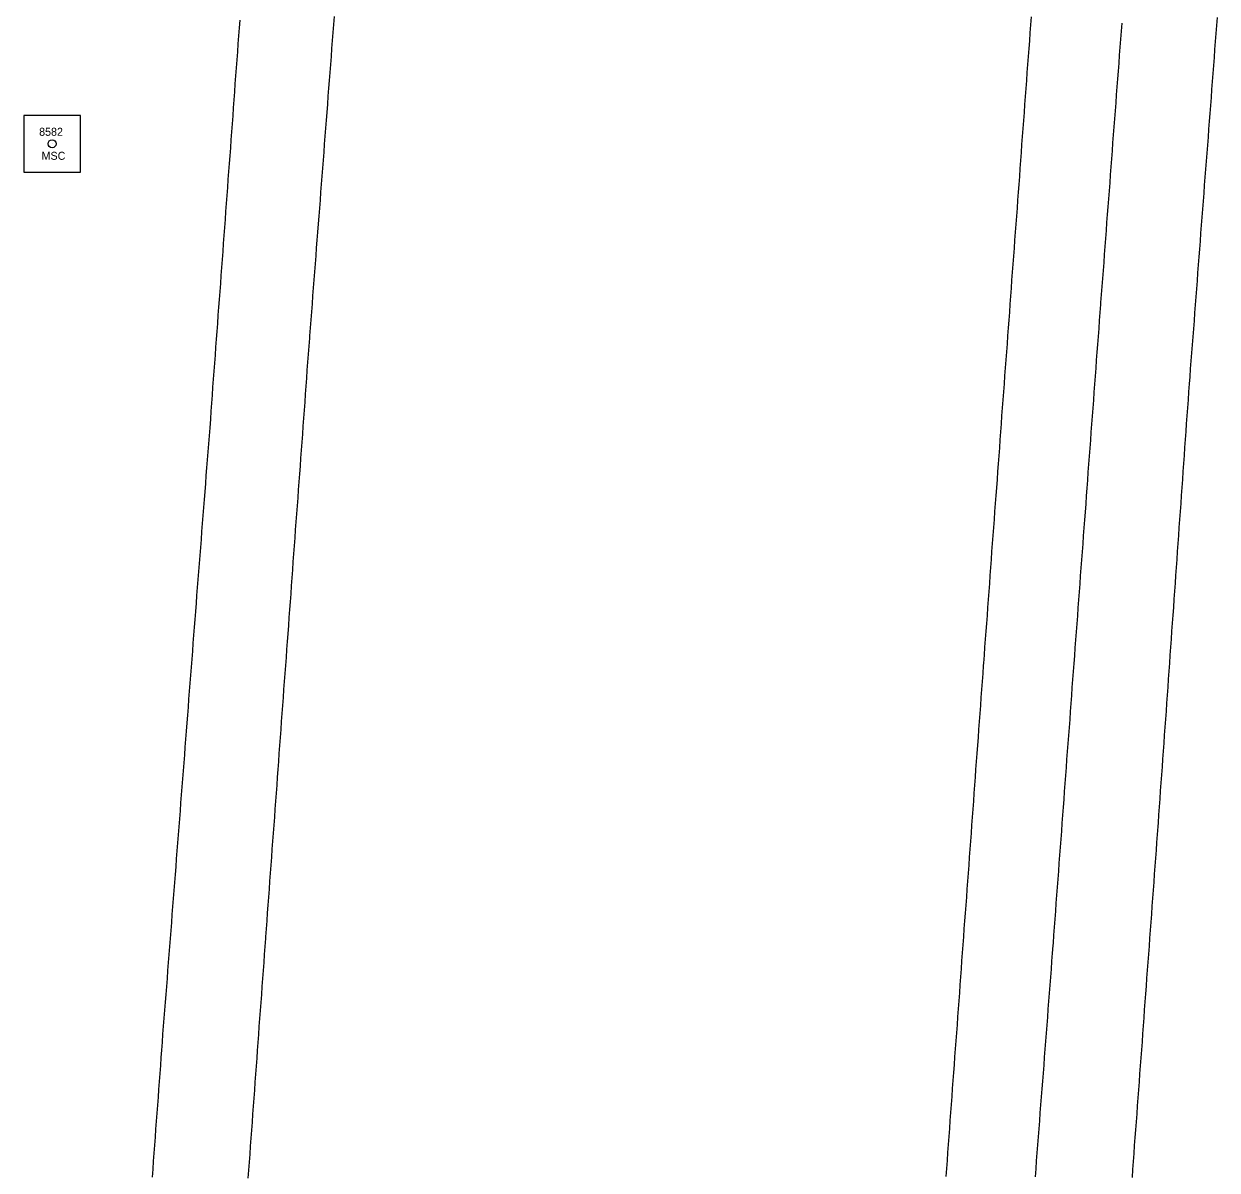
# Model space of a CAD drawing. Extents: x 205929 to 2357175, y -1785700 to 846739.
# Drawn here: x 2023382 to 2023531.1, y 809217.5 to 809360.7 of the extents above; entities that cross this region are included whole.
import ezdxf

# ---------------------------------------------------------------- set-up
doc = ezdxf.new("R2010")
doc.units = 0
for name, color, linetype in [('RD_HC_Survey', 7, 'Continuous'), ('RD_HC_txCode', 7, 'Continuous'), ('RD_Sketch1', 7, 'Continuous'), ('RD_SMD_Locator', 7, 'Continuous')]:
    doc.layers.add(name, color=color, linetype=linetype)

msp = doc.modelspace()

# ---------------------------------------------------------------- linework, layer by layer
at = {"layer": 'RD_HC_Survey'}
msp.add_lwpolyline([(2023389.03, 809349.29), (2023381.96, 809349.29), (2023381.96, 809342.22), (2023389.03, 809342.22)], close=True, dxfattribs=at)
msp.add_circle((2023385.5, 809345.75), 0.5, dxfattribs=at)
at = {"layer": 'RD_Sketch1'}
for points in [[(2023408.94, 809361.21), (2023408.87, 809360.22), (2023408.8, 809359.22), (2023408.72, 809358.22), (2023408.65, 809357.23), (2023408.57, 809356.23), (2023408.5, 809355.23), (2023408.43, 809354.23), (2023408.35, 809353.24), (2023408.28, 809352.24), (2023408.21, 809351.24), (2023408.13, 809350.25), (2023408.06, 809349.25), (2023407.99, 809348.25), (2023407.91, 809347.25), (2023407.84, 809346.26), (2023407.77, 809345.26), (2023407.69, 809344.26), (2023407.62, 809343.27), (2023407.55, 809342.27), (2023407.47, 809341.27), (2023407.4, 809340.27), (2023407.33, 809339.28), (2023407.25, 809338.28), (2023407.18, 809337.28), (2023407.11, 809336.29), (2023407.03, 809335.29), (2023406.96, 809334.29), (2023406.88, 809333.29), (2023406.81, 809332.3), (2023406.74, 809331.3), (2023406.66, 809330.3), (2023406.59, 809329.3), (2023406.52, 809328.31), (2023406.44, 809327.31), (2023406.37, 809326.31), (2023406.37, 809326.31), (2023406.3, 809325.32), (2023406.22, 809324.32), (2023406.15, 809323.32), (2023406.08, 809322.32), (2023406, 809321.33), (2023405.93, 809320.33), (2023405.86, 809319.33), (2023405.78, 809318.34), (2023405.71, 809317.34), (2023405.64, 809316.34), (2023405.56, 809315.34), (2023405.49, 809314.35), (2023405.41, 809313.35), (2023405.34, 809312.35), (2023405.27, 809311.36), (2023405.19, 809310.27), (2023405.11, 809309.27), (2023405.03, 809308.27), (2023404.96, 809307.28), (2023404.88, 809306.28), (2023404.8, 809305.28), (2023404.72, 809304.29), (2023404.65, 809303.29), (2023404.57, 809302.29), (2023404.49, 809301.3), (2023404.41, 809300.3), (2023404.34, 809299.3), (2023404.26, 809298.31), (2023404.18, 809297.31), (2023404.11, 809296.31), (2023404.03, 809295.32), (2023403.95, 809294.32), (2023403.87, 809293.32), (2023403.8, 809292.33), (2023403.72, 809291.33), (2023403.64, 809290.33), (2023403.56, 809289.33), (2023403.49, 809288.34), (2023403.41, 809287.34), (2023403.33, 809286.34), (2023403.26, 809285.35), (2023403.18, 809284.35), (2023403.1, 809283.35), (2023403.02, 809282.36), (2023402.95, 809281.36), (2023402.87, 809280.36), (2023402.79, 809279.37), (2023402.71, 809278.37), (2023402.64, 809277.37), (2023402.56, 809276.38), (2023402.48, 809275.38), (2023402.41, 809274.38), (2023402.33, 809273.39), (2023402.25, 809272.39), (2023402.17, 809271.39), (2023402.1, 809270.39), (2023402.02, 809269.4), (2023401.94, 809268.4), (2023401.86, 809267.4), (2023401.79, 809266.41), (2023401.71, 809265.41), (2023401.63, 809264.41), (2023401.56, 809263.42), (2023401.48, 809262.42), (2023401.48, 809262.42), (2023401.4, 809261.42), (2023401.32, 809260.43), (2023401.25, 809259.43), (2023401.17, 809258.43), (2023401.09, 809257.44), (2023401.01, 809256.44), (2023400.94, 809255.44), (2023400.86, 809254.45), (2023400.78, 809253.45), (2023400.71, 809252.45), (2023400.63, 809251.45), (2023400.55, 809250.46), (2023400.47, 809249.46), (2023400.4, 809248.46), (2023400.32, 809247.47), (2023400.24, 809246.47), (2023400.16, 809245.47), (2023400.09, 809244.48), (2023400.01, 809243.48), (2023399.93, 809242.48), (2023399.86, 809241.49), (2023399.78, 809240.49), (2023399.7, 809239.49), (2023399.62, 809238.5), (2023399.55, 809237.5), (2023399.47, 809236.5), (2023399.39, 809235.51), (2023399.31, 809234.51), (2023399.24, 809233.51), (2023399.16, 809232.51), (2023399.09, 809231.61), (2023399.02, 809230.61), (2023398.94, 809229.62), (2023398.87, 809228.62), (2023398.8, 809227.62), (2023398.73, 809226.63), (2023398.65, 809225.63), (2023398.58, 809224.63), (2023398.51, 809223.63), (2023398.43, 809222.64), (2023398.36, 809221.64), (2023398.29, 809220.64), (2023398.22, 809219.64), (2023398.14, 809218.65), (2023398.07, 809217.65), (2023398, 809216.65)], [(2023420.74, 809361.65), (2023420.66, 809360.65), (2023420.59, 809359.65), (2023420.51, 809358.66), (2023420.43, 809357.66), (2023420.36, 809356.66), (2023420.28, 809355.67), (2023420.2, 809354.67), (2023420.13, 809353.67), (2023420.05, 809352.68), (2023419.97, 809351.68), (2023419.9, 809350.68), (2023419.82, 809349.68), (2023419.74, 809348.69), (2023419.67, 809347.69), (2023419.59, 809346.69), (2023419.51, 809345.7), (2023419.44, 809344.7), (2023419.36, 809343.7), (2023419.28, 809342.71), (2023419.21, 809341.71), (2023419.13, 809340.71), (2023419.05, 809339.71), (2023418.98, 809338.72), (2023418.9, 809337.72), (2023418.82, 809336.72), (2023418.75, 809335.73), (2023418.67, 809334.73), (2023418.59, 809333.73), (2023418.51, 809332.74), (2023418.44, 809331.74), (2023418.36, 809330.74), (2023418.28, 809329.75), (2023418.21, 809328.75), (2023418.13, 809327.75), (2023418.05, 809326.75), (2023417.98, 809325.76), (2023417.9, 809324.76), (2023417.82, 809323.76), (2023417.82, 809323.76), (2023417.75, 809322.77), (2023417.67, 809321.77), (2023417.65, 809321.45), (2023417.57, 809320.45), (2023417.5, 809319.45), (2023417.43, 809318.46), (2023417.35, 809317.46), (2023417.28, 809316.46), (2023417.21, 809315.46), (2023417.13, 809314.47), (2023417.06, 809313.47), (2023416.99, 809312.47), (2023416.92, 809311.48), (2023416.84, 809310.48), (2023416.77, 809309.48), (2023416.7, 809308.48), (2023416.62, 809307.49), (2023416.55, 809306.49), (2023416.48, 809305.49), (2023416.4, 809304.5), (2023416.33, 809303.5), (2023416.26, 809302.5), (2023416.19, 809301.5), (2023416.11, 809300.51), (2023416.04, 809299.51), (2023415.97, 809298.51), (2023415.89, 809297.52), (2023415.82, 809296.52), (2023415.75, 809295.52), (2023415.67, 809294.52), (2023415.6, 809293.53), (2023415.53, 809292.53), (2023415.46, 809291.53), (2023415.38, 809290.54), (2023415.31, 809289.54), (2023415.24, 809288.54), (2023415.16, 809287.55), (2023415.09, 809286.55), (2023415.02, 809285.55), (2023414.94, 809284.55), (2023414.87, 809283.56), (2023414.8, 809282.56), (2023414.73, 809281.56), (2023414.65, 809280.57), (2023414.58, 809279.57), (2023414.51, 809278.57), (2023414.43, 809277.57), (2023414.36, 809276.58), (2023414.29, 809275.58), (2023414.22, 809274.58), (2023414.14, 809273.59), (2023414.07, 809272.59), (2023414, 809271.59), (2023413.92, 809270.59), (2023413.85, 809269.6), (2023413.78, 809268.6), (2023413.7, 809267.6), (2023413.63, 809266.61), (2023413.56, 809265.61), (2023413.49, 809264.61), (2023413.41, 809263.61), (2023413.34, 809262.62), (2023413.27, 809261.62), (2023413.19, 809260.62), (2023413.19, 809260.62), (2023413.12, 809259.63), (2023413.05, 809258.63), (2023412.97, 809257.63), (2023412.9, 809256.63), (2023412.83, 809255.64), (2023412.76, 809254.64), (2023412.68, 809253.64), (2023412.61, 809252.65), (2023412.54, 809251.65), (2023412.46, 809250.65), (2023412.39, 809249.66), (2023412.32, 809248.66), (2023412.24, 809247.66), (2023412.17, 809246.66), (2023412.16, 809246.46), (2023412.08, 809245.46), (2023412.01, 809244.46), (2023411.94, 809243.46), (2023411.86, 809242.47), (2023411.79, 809241.47), (2023411.72, 809240.47), (2023411.65, 809239.48), (2023411.57, 809238.48), (2023411.5, 809237.48), (2023411.43, 809236.48), (2023411.35, 809235.49), (2023411.28, 809234.49), (2023411.21, 809233.49), (2023411.14, 809232.49), (2023411.06, 809231.5), (2023410.99, 809230.5), (2023410.92, 809229.5), (2023410.84, 809228.51), (2023410.77, 809227.51), (2023410.7, 809226.51), (2023410.63, 809225.51), (2023410.55, 809224.52), (2023410.48, 809223.52), (2023410.41, 809222.52), (2023410.33, 809221.52), (2023410.26, 809220.53), (2023410.19, 809219.53), (2023410.12, 809218.53), (2023410.04, 809217.54), (2023409.97, 809216.54)], [(2023507.85, 809361.62), (2023507.78, 809360.63), (2023507.7, 809359.63), (2023507.63, 809358.63), (2023507.56, 809357.64), (2023507.48, 809356.64), (2023507.41, 809355.64), (2023507.33, 809354.64), (2023507.26, 809353.65), (2023507.19, 809352.65), (2023507.11, 809351.65), (2023507.04, 809350.66), (2023506.97, 809349.66), (2023506.89, 809348.66), (2023506.82, 809347.66), (2023506.75, 809346.67), (2023506.67, 809345.67), (2023506.6, 809344.67), (2023506.53, 809343.68), (2023506.45, 809342.68), (2023506.38, 809341.68), (2023506.31, 809340.68), (2023506.23, 809339.69), (2023506.16, 809338.69), (2023506.09, 809337.69), (2023506.01, 809336.7), (2023505.94, 809335.7), (2023505.86, 809334.7), (2023505.79, 809333.7), (2023505.72, 809332.71), (2023505.64, 809331.71), (2023505.57, 809330.71), (2023505.5, 809329.72), (2023505.42, 809328.72), (2023505.35, 809327.72), (2023505.28, 809326.72), (2023505.2, 809325.73), (2023505.13, 809324.73), (2023505.06, 809323.73), (2023504.98, 809322.74), (2023504.91, 809321.74), (2023504.84, 809320.74), (2023504.76, 809319.74), (2023504.69, 809318.75), (2023504.61, 809317.75), (2023504.54, 809316.75), (2023504.47, 809315.76), (2023504.39, 809314.76), (2023504.32, 809313.76), (2023504.25, 809312.76), (2023504.25, 809312.76), (2023504.17, 809311.77), (2023504.1, 809310.77), (2023504.03, 809309.77), (2023503.95, 809308.78), (2023503.88, 809307.78), (2023503.81, 809306.78), (2023503.73, 809305.78), (2023503.66, 809304.79), (2023503.59, 809303.79), (2023503.51, 809302.79), (2023503.44, 809301.8), (2023503.36, 809300.8), (2023503.29, 809299.8), (2023503.22, 809298.8), (2023503.14, 809297.81), (2023503.07, 809296.81), (2023503, 809295.81), (2023502.92, 809294.82), (2023502.85, 809293.82), (2023502.78, 809292.82), (2023502.7, 809291.83), (2023502.63, 809290.83), (2023502.56, 809289.83), (2023502.48, 809288.83), (2023502.41, 809287.84), (2023502.34, 809286.84), (2023502.26, 809285.84), (2023502.19, 809284.85), (2023502.12, 809283.85), (2023502.04, 809282.85), (2023501.97, 809281.85), (2023501.89, 809280.86), (2023501.87, 809280.57), (2023501.8, 809279.57), (2023501.73, 809278.57), (2023501.65, 809277.58), (2023501.58, 809276.58), (2023501.51, 809275.58), (2023501.43, 809274.58), (2023501.36, 809273.59), (2023501.29, 809272.59), (2023501.22, 809271.59), (2023501.14, 809270.6), (2023501.07, 809269.6), (2023501, 809268.6), (2023500.92, 809267.6), (2023500.85, 809266.61), (2023500.78, 809265.61), (2023500.7, 809264.61), (2023500.63, 809263.61), (2023500.56, 809262.62), (2023500.49, 809261.62), (2023500.41, 809260.62), (2023500.34, 809259.63), (2023500.27, 809258.63), (2023500.19, 809257.63), (2023500.12, 809256.63), (2023500.05, 809255.64), (2023499.97, 809254.64), (2023499.9, 809253.64), (2023499.83, 809252.64), (2023499.76, 809251.65), (2023499.68, 809250.65), (2023499.61, 809249.65), (2023499.61, 809249.65), (2023499.54, 809248.66), (2023499.46, 809247.66), (2023499.39, 809246.66), (2023499.32, 809245.66), (2023499.24, 809244.67), (2023499.17, 809243.67), (2023499.1, 809242.67), (2023499.02, 809241.67), (2023498.95, 809240.68), (2023498.88, 809239.68), (2023498.81, 809238.68), (2023498.73, 809237.69), (2023498.66, 809236.69), (2023498.59, 809235.69), (2023498.51, 809234.69), (2023498.44, 809233.7), (2023498.37, 809232.7), (2023498.29, 809231.7), (2023498.22, 809230.7), (2023498.15, 809229.71), (2023498.08, 809228.71), (2023498, 809227.71), (2023497.93, 809226.72), (2023497.86, 809225.72), (2023497.78, 809224.72), (2023497.71, 809223.72), (2023497.64, 809222.73), (2023497.56, 809221.73), (2023497.49, 809220.73), (2023497.42, 809219.73), (2023497.34, 809218.74), (2023497.27, 809217.74), (2023497.2, 809216.74)], [(2023531.1, 809361.52), (2023531.02, 809360.52), (2023530.94, 809359.52), (2023530.87, 809358.53), (2023530.79, 809357.53), (2023530.72, 809356.53), (2023530.64, 809355.54), (2023530.56, 809354.54), (2023530.49, 809353.54), (2023530.41, 809352.54), (2023530.34, 809351.55), (2023530.26, 809350.55), (2023530.26, 809350.55), (2023530.18, 809349.55), (2023530.11, 809348.56), (2023530.03, 809347.56), (2023529.96, 809346.56), (2023529.88, 809345.56), (2023529.8, 809344.57), (2023529.73, 809343.57), (2023529.65, 809342.57), (2023529.57, 809341.58), (2023529.5, 809340.58), (2023529.42, 809339.58), (2023529.35, 809338.59), (2023529.27, 809337.59), (2023529.19, 809336.59), (2023529.12, 809335.59), (2023529.04, 809334.6), (2023528.97, 809333.6), (2023528.89, 809332.6), (2023528.81, 809331.61), (2023528.74, 809330.61), (2023528.66, 809329.61), (2023528.59, 809328.62), (2023528.51, 809327.62), (2023528.43, 809326.62), (2023528.36, 809325.62), (2023528.28, 809324.63), (2023528.21, 809323.63), (2023528.13, 809322.63), (2023528.05, 809321.64), (2023527.98, 809320.64), (2023527.9, 809319.64), (2023527.82, 809318.64), (2023527.75, 809317.65), (2023527.67, 809316.65), (2023527.61, 809315.77), (2023527.53, 809314.77), (2023527.46, 809313.78), (2023527.39, 809312.78), (2023527.32, 809311.78), (2023527.25, 809310.78), (2023527.18, 809309.79), (2023527.11, 809308.79), (2023527.04, 809307.79), (2023526.97, 809306.8), (2023526.9, 809305.8), (2023526.83, 809304.8), (2023526.76, 809303.8), (2023526.69, 809302.81), (2023526.62, 809301.81), (2023526.55, 809300.81), (2023526.47, 809299.81), (2023526.4, 809298.82), (2023526.33, 809297.82), (2023526.26, 809296.82), (2023526.19, 809295.82), (2023526.12, 809294.83), (2023526.05, 809293.83), (2023525.98, 809292.83), (2023525.91, 809291.83), (2023525.84, 809290.84), (2023525.77, 809289.84), (2023525.7, 809288.84), (2023525.63, 809287.84), (2023525.56, 809286.85), (2023525.56, 809286.85), (2023525.49, 809285.85), (2023525.41, 809284.85), (2023525.34, 809283.85), (2023525.27, 809282.86), (2023525.2, 809281.86), (2023525.13, 809280.86), (2023525.06, 809279.86), (2023524.99, 809278.87), (2023524.92, 809277.87), (2023524.85, 809276.87), (2023524.78, 809275.88), (2023524.71, 809274.88), (2023524.64, 809273.88), (2023524.57, 809272.88), (2023524.5, 809271.89), (2023524.43, 809270.89), (2023524.35, 809269.89), (2023524.28, 809268.89), (2023524.21, 809267.9), (2023524.14, 809266.9), (2023524.07, 809265.9), (2023524, 809264.9), (2023523.93, 809263.91), (2023523.86, 809262.91), (2023523.79, 809261.91), (2023523.72, 809260.91), (2023523.69, 809260.48), (2023523.61, 809259.48), (2023523.54, 809258.48), (2023523.47, 809257.49), (2023523.39, 809256.49), (2023523.32, 809255.49), (2023523.25, 809254.49), (2023523.17, 809253.5), (2023523.1, 809252.5), (2023523.03, 809251.5), (2023522.95, 809250.51), (2023522.88, 809249.51), (2023522.81, 809248.51), (2023522.73, 809247.51), (2023522.66, 809246.52), (2023522.59, 809245.52), (2023522.51, 809244.52), (2023522.44, 809243.53), (2023522.37, 809242.53), (2023522.29, 809241.53), (2023522.22, 809240.53), (2023522.15, 809239.54), (2023522.07, 809238.54), (2023522, 809237.54), (2023521.93, 809236.55), (2023521.85, 809235.55), (2023521.78, 809234.55), (2023521.71, 809233.55), (2023521.63, 809232.56), (2023521.56, 809231.56), (2023521.49, 809230.56), (2023521.41, 809229.56), (2023521.34, 809228.57), (2023521.27, 809227.57), (2023521.19, 809226.57), (2023521.12, 809225.58), (2023521.05, 809224.58), (2023520.97, 809223.58), (2023520.97, 809223.58), (2023520.9, 809222.58), (2023520.83, 809221.59), (2023520.75, 809220.59), (2023520.68, 809219.59), (2023520.61, 809218.6), (2023520.53, 809217.6), (2023520.46, 809216.6)], [(2023519.17, 809360.82), (2023519.1, 809359.83), (2023519.02, 809358.83), (2023518.95, 809357.83), (2023518.87, 809356.84), (2023518.8, 809355.84), (2023518.72, 809354.84), (2023518.65, 809353.85), (2023518.57, 809352.85), (2023518.5, 809351.85), (2023518.42, 809350.85), (2023518.35, 809349.86), (2023518.27, 809348.86), (2023518.19, 809347.86), (2023518.12, 809346.87), (2023518.04, 809345.87), (2023517.97, 809344.87), (2023517.89, 809343.88), (2023517.82, 809342.88), (2023517.74, 809341.88), (2023517.67, 809340.88), (2023517.59, 809339.89), (2023517.52, 809338.89), (2023517.44, 809337.89), (2023517.37, 809336.9), (2023517.29, 809335.9), (2023517.22, 809334.9), (2023517.14, 809333.9), (2023517.07, 809332.91), (2023516.99, 809331.91), (2023516.92, 809330.91), (2023516.84, 809329.92), (2023516.77, 809328.92), (2023516.69, 809327.92), (2023516.61, 809326.93), (2023516.54, 809325.93), (2023516.52, 809325.68), (2023516.45, 809324.68), (2023516.37, 809323.69), (2023516.3, 809322.69), (2023516.22, 809321.69), (2023516.15, 809320.69), (2023516.08, 809319.7), (2023516, 809318.7), (2023515.93, 809317.7), (2023515.85, 809316.71), (2023515.78, 809315.71), (2023515.71, 809314.71), (2023515.63, 809313.71), (2023515.56, 809312.72), (2023515.56, 809312.72), (2023515.48, 809311.72), (2023515.41, 809310.72), (2023515.33, 809309.73), (2023515.26, 809308.73), (2023515.19, 809307.73), (2023515.11, 809306.73), (2023515.04, 809305.74), (2023514.96, 809304.74), (2023514.89, 809303.74), (2023514.82, 809302.74), (2023514.74, 809301.75), (2023514.67, 809300.75), (2023514.59, 809299.75), (2023514.52, 809298.76), (2023514.44, 809297.76), (2023514.37, 809296.76), (2023514.3, 809295.76), (2023514.22, 809294.77), (2023514.15, 809293.77), (2023514.07, 809292.77), (2023514, 809291.78), (2023513.93, 809290.78), (2023513.85, 809289.78), (2023513.78, 809288.78), (2023513.7, 809287.79), (2023513.63, 809286.79), (2023513.56, 809285.79), (2023513.48, 809284.8), (2023513.41, 809283.8), (2023513.33, 809282.8), (2023513.26, 809281.8), (2023513.18, 809280.81), (2023513.11, 809279.81), (2023513.04, 809278.81), (2023512.96, 809277.81), (2023512.89, 809276.82), (2023512.81, 809275.82), (2023512.74, 809274.82), (2023512.67, 809273.83), (2023512.59, 809272.83), (2023512.52, 809271.83), (2023512.44, 809270.83), (2023512.37, 809269.84), (2023512.29, 809268.84), (2023512.22, 809267.84), (2023512.15, 809266.85), (2023512.07, 809265.85), (2023512, 809264.85), (2023511.92, 809263.85), (2023511.85, 809262.86), (2023511.78, 809261.86), (2023511.7, 809260.86), (2023511.63, 809259.87), (2023511.55, 809258.87), (2023511.48, 809257.87), (2023511.41, 809256.87), (2023511.33, 809255.88), (2023511.26, 809254.88), (2023511.18, 809253.88), (2023511.11, 809252.88), (2023511.03, 809251.89), (2023510.96, 809250.89), (2023510.89, 809249.89), (2023510.81, 809248.9), (2023510.81, 809248.9), (2023510.74, 809247.9), (2023510.66, 809246.9), (2023510.59, 809245.9), (2023510.57, 809245.61), (2023510.49, 809244.62), (2023510.41, 809243.62), (2023510.34, 809242.62), (2023510.26, 809241.63), (2023510.18, 809240.63), (2023510.11, 809239.63), (2023510.03, 809238.63), (2023509.95, 809237.64), (2023509.88, 809236.64), (2023509.8, 809235.64), (2023509.72, 809234.65), (2023509.65, 809233.65), (2023509.57, 809232.65), (2023509.49, 809231.66), (2023509.42, 809230.66), (2023509.34, 809229.66), (2023509.26, 809228.66), (2023509.18, 809227.67), (2023509.11, 809226.67), (2023509.03, 809225.67), (2023508.95, 809224.68), (2023508.88, 809223.68), (2023508.8, 809222.68), (2023508.72, 809221.69), (2023508.65, 809220.69), (2023508.57, 809219.69), (2023508.49, 809218.7), (2023508.42, 809217.7), (2023508.34, 809216.7)]]:
    msp.add_lwpolyline(points, dxfattribs=at)
at = {"layer": 'RD_SMD_Locator'}
msp.add_circle((2023385.5, 809345.75), 0.001, dxfattribs=at)

# ---------------------------------------------------------------- texts
at = {"layer": 'RD_HC_txCode'}
for s, p in [('8582', (2023383.87, 809346.75)), ('MSC', (2023384.18, 809343.75))]:
    msp.add_text(s, height=1, dxfattribs=at).set_placement(p)

doc.saveas('drawing.dxf')
